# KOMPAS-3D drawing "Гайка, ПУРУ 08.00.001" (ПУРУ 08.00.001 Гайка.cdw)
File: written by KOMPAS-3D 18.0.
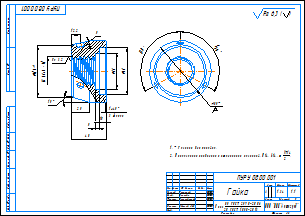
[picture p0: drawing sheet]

Sheet 1: A3, landscape

Document properties: Автор: cons; Масса: 1.33518; Параметр неуказанной шероховатости: Ra 6,3; Полное имя файла: ..\ПУРУ 08.00.001 Гайка.m3d

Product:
- Part/product: Гайка  | designation ПУРУ 08.00.001
    Материал: Круг$d85 ГОСТ 2590-2006;20 ГОСТ 1050-2013$ (density 7859 kg/m3)
    Масса: 1.33518
    Раздел спецификации: Детали
    Форматы листов документа: A3
    source file: ..\ПУРУ 08.00.001 Гайка.m3d, ПУРУ 08.00.001 Гайка.cdw

Title block, sheet 1: Наименование: Гайка; designation: ПУРУ 08.00.001; Материал: Круг 85 ГОСТ 2590-2006 20 ГОСТ 1050-2013; Масса: 1,34; sheets: 1; organisation: ООО "НПЦ"Антиград"; Форматы листов документа: A3; revision letter: А; stored path: D:\РУ 00.00.000 Установка противоградовая ручная\РУ 08.00.000 Рукоятка\Чертежи\РУ 08.00.001 Втулка.cdw; Разработал: Грицунов; Проверил: Налоева; Т. контр.: Семеновский; Н. контр.: Абшаев А.М.; Разработал, date: 07.07.2017; Проверил, date: 07.07.2017; Т. контр., date: 07.07.2017; Н. контр., date: 07.07.2017

Views: Вид 1, Местный разрез 1, Сзади, Проекционный вид 2
Referenced files in D:\Град\ПУРУ 00.00.000 Установка пусковая ручная Элия-Р\ПУРУ 08.00.000 Рукоятка\: ПУРУ 08.00.001 Гайка.m3d
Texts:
  Tr 40х6
  Ra 3,2
  Ra 6,3
  Ra 6,3 ( )
Dimensions and other numbers on the sheet: 1; 3 фаски; 25; 48; -7Н; 71,6; 65; 10; 50; 5; 12,2; 85; 120; 1:1; 1,34; 07.07.2017

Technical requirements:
  * Размеры для справок.
  Неуказанные предельные отклонения размеров: H14, h14,    IT14 2 .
